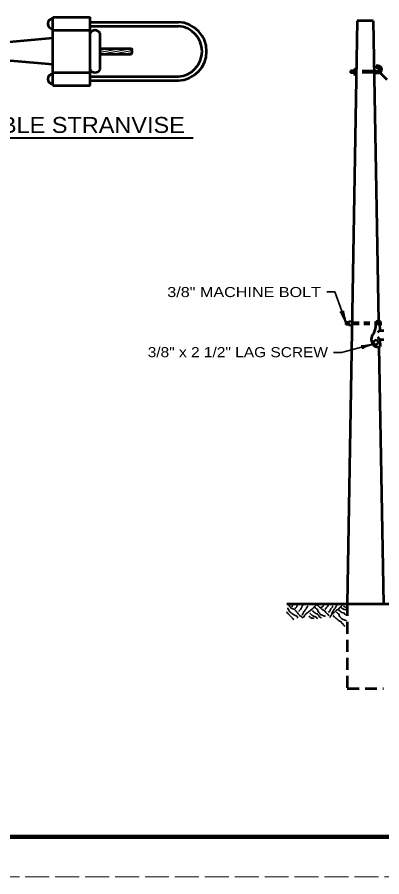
# Model space of a CAD drawing. Extents: x -1 to 679, y 0 to 440.
# Drawn here: x 228.3 to 319.7, y 0.2 to 215.6 of the extents above; entities that cross this region are included whole.
import ezdxf
from ezdxf.enums import TextEntityAlignment as Align

# ---------------------------------------------------------------- set-up
doc = ezdxf.new("R2010")
doc.units = 0
for name, pattern in [('LONG_DASHED', [7.5, 6, -1.5]), ('MEDIUM_DASHED', [4.5, 3, -1.5]), ('SHORT_DASHED', [2.7, 1.5, -1.2])]:
    doc.linetypes.add(name, pattern=pattern)
doc.layers.add('1', color=7, linetype='Continuous', lineweight=53)
doc.layers.add('61', color=7, linetype='Continuous', lineweight=35)

msp = doc.modelspace()

# ---------------------------------------------------------------- linework, layer by layer
at = {"layer": '1'}
for p, q in [((237.256, 215.614), (246.596, 215.614)), ((237.256, 212.334), (237.256, 215.614)), ((246.596, 198.474), (246.596, 215.614)), ((246.596, 214.354), (268.756, 214.354)), ((246.596, 213.354), (268.756, 213.354)), ((313.579, 214.715), (311.019, 68.575)), ((317.599, 214.715), (313.579, 214.715)), ((317.599, 214.715), (318.919, 139.375)), ((237.256, 212.334), (246.596, 212.334)), ((249.116, 202.514), (249.116, 211.594)), ((237.256, 210.334), (213.656, 208.254)), ((249.116, 207.754), (257.016, 207.754)), ((237.256, 203.774), (213.656, 205.834)), ((249.116, 206.354), (257.016, 206.354)), ((313.099, 202.895), (313.099, 200.895)), ((313.099, 202.895), (313.359, 202.895)), ((318.839, 203.415), (318.319, 203.415)), ((318.839, 202.895), (318.319, 202.895)), ((237.256, 201.754), (246.596, 201.754)), ((246.596, 200.754), (268.756, 200.754)), ((312.599, 202.155), (311.839, 202.155)), ((311.839, 202.155), (311.839, 201.635)), ((312.599, 201.635), (311.839, 201.635)), ((312.599, 202.395), (312.599, 201.395)), ((312.599, 202.395), (313.079, 202.395)), ((312.599, 201.395), (313.099, 201.395)), ((313.099, 200.895), (313.319, 200.895)), ((317.819, 202.155), (318.839, 202.155)), ((317.839, 201.635), (318.939, 201.635)), ((318.819, 202.135), (320.959, 200.015)), ((237.256, 198.474), (246.596, 198.474)), ((246.596, 199.734), (268.756, 199.734)), ((311.479, 139.115), (310.739, 139.115)), ((310.739, 139.115), (310.739, 138.615)), ((311.479, 138.615), (310.739, 138.615)), ((311.479, 138.375), (311.479, 139.375)), ((319.439, 139.375), (318.859, 139.375)), ((319.179, 138.955), (319.199, 137.135)), ((319.439, 138.375), (319.179, 138.375)), ((319.439, 139.375), (319.439, 138.375)), ((319.199, 137.135), (318.679, 136.595)), ((319.199, 137.135), (320.259, 137.135)), ((317.459, 134.275), (318.279, 134.855)), ((317.459, 134.275), (318.039, 133.435)), ((318.039, 133.435), (318.859, 134.015)), ((318.279, 134.855), (318.859, 134.015)), ((319.239, 134.875), (318.719, 135.415)), ((319.239, 134.875), (319.279, 133.115)), ((319.239, 134.875), (320.259, 134.875)), ((319.019, 133.035), (320.159, 68.575)), ((295.899, 68.575), (484.219, 68.575))]:
    msp.add_line(p, q, dxfattribs=at)
at = {"layer": '1', "lineweight": 25}
for p, q in [((249.116, 206.354), (257.016, 207.754)), ((249.116, 207.374), (251.296, 207.754)), ((249.116, 206.854), (254.156, 207.754)), ((251.976, 206.354), (256.996, 207.254)), ((254.836, 206.354), (257.076, 206.754))]:
    msp.add_line(p, q, dxfattribs=at)
at = {"layer": '1', "linetype": 'MEDIUM_DASHED', "lineweight": 40}
for p, q in [((317.839, 201.635), (313.339, 201.635)), ((317.819, 202.155), (313.359, 202.155))]:
    msp.add_line(p, q, dxfattribs=at)
at = {"layer": '1', "lineweight": 40}
for p, q in [((215.436, 185.414), (272.476, 185.414)), ((312.259, 139.375), (311.479, 139.375)), ((312.239, 138.375), (311.479, 138.375))]:
    msp.add_line(p, q, dxfattribs=at)
at = {"layer": '1', "linetype": 'SHORT_DASHED', "lineweight": 40}
for p, q in [((319.439, 138.615), (312.239, 138.615)), ((319.419, 139.115), (312.259, 139.115))]:
    msp.add_line(p, q, dxfattribs=at)
at = {"layer": '1', "linetype": 'MEDIUM_DASHED'}
for p, q in [((311.019, 68.575), (311.019, 47.415)), ((311.019, 47.415), (320.159, 47.415))]:
    msp.add_line(p, q, dxfattribs=at)
at = {"layer": '1'}
msp.add_lwpolyline([(237.256, 198.474), (237.256, 201.754), (237.256, 212.334)], dxfattribs=at)
at = {"layer": '1', "lineweight": 35}
for points in [[(310.699, 139.175), (307.939, 146.755), (305.919, 146.755)], [(317.439, 133.655), (309.659, 131.575), (307.639, 131.575)]]:
    msp.add_lwpolyline(points, dxfattribs=at)
at = {"layer": '1'}
for centre, radius, start, end in [((237.264, 213.982), 1.26, 90, 270), ((268.507, 207.052), 7.312, 272.01017, 87.98983), ((268.367, 207.052), 6.312, 273.59778, 86.40223), ((247.848, 210.916), 1.428, 28.07249, 151.92751), ((247.848, 203.187), 1.428, 208.07249, 331.92751), ((318.612, 203.153), 0.381, 138.58649, 221.41351), ((318.808, 202.518), 0.887, 278.54206, 88.56984), ((318.7, 202.523), 0.4, 289.03349, 70.96651), ((237.264, 200.122), 1.26, 90, 270), ((314.182, 138.306), 4.014, 331.99837, 353.85569), ((320.301, 138.299), 2.168, 151.6071, 191.23066), ((318.674, 138.91), 0.505, 5.14198, 123.76222), ((319.372, 134.854), 2.272, 136.38146, 225.27926), ((318.67, 134.82), 1.818, 240.4205, 289.57853)]:
    msp.add_arc(centre, radius, start, end, dxfattribs=at)
at = {"layer": '1', "lineweight": 40}
for centre, major_axis, ratio, start_param, end_param in [((310.056, 140.123), (0.764, -1.638), 0.122415, 0.8963533, 3.1415927), ((310.508, 140.319), (0.439, -1.724), 0.07063, 3.1407148, 5.41811), ((316.294, 133.568), (-1.756, -0.287), 0.07063, 6.2823074, 8.5597026), ((316.45, 133.101), (1.698, 0.618), 0.122415, 0.8963533, 3.1415927)]:
    msp.add_ellipse(centre, major_axis=major_axis, ratio=ratio, start_param=start_param, end_param=end_param, dxfattribs=at)
at = {"layer": '1'}
msp.add_spline([(257.016, 207.754), (257.096, 207.614), (257.036, 207.534), (257.056, 207.374), (256.996, 207.254), (257.076, 207.134), (257.036, 207.034), (257.076, 206.854), (257.056, 206.714), (256.996, 206.594), (257.016, 206.534), (257.016, 206.354)], degree=3, dxfattribs=at)
at = {"layer": '1', "lineweight": 35}
for points in [[(296.139, 67.635), (296.279, 67.255), (296.539, 66.835), (296.859, 66.415), (297.179, 66.215), (297.719, 65.835), (298.599, 65.255), (298.619, 64.995)], [(296.359, 68.455), (297.019, 67.555), (297.859, 67.155), (298.359, 66.635), (298.619, 66.315), (298.939, 65.935), (299.199, 65.615), (299.599, 65.415), (299.919, 65.035)], [(297.519, 68.375), (297.439, 68.255), (297.399, 68.255), (297.339, 68.175), (297.179, 67.895), (297.139, 67.835)], [(298.719, 68.335), (298.519, 68.175), (298.459, 68.015), (298.399, 67.835), (298.279, 67.695), (298.199, 67.635), (297.919, 67.415)], [(299.979, 68.255), (299.779, 68.055), (299.659, 67.735), (299.499, 67.415), (299.139, 67.015), (299.019, 66.835), (298.939, 66.735)], [(301.239, 68.055), (300.939, 67.735), (300.779, 67.375), (300.519, 67.095), (300.339, 66.795), (300.139, 66.575), (300.039, 66.335), (299.919, 66.115), (299.759, 65.795)], [(303.179, 68.455), (303.179, 68.315), (303.099, 68.135), (302.979, 67.995), (302.859, 67.875), (302.599, 67.615), (302.399, 67.415), (301.819, 66.975), (301.499, 66.715), (300.859, 66.195), (300.599, 65.935), (300.459, 65.735), (300.279, 65.475), (300.079, 65.155)], [(302.339, 66.955), (302.819, 66.475), (302.919, 66.435), (303.019, 66.335), (303.439, 66.095), (303.939, 65.635), (304.099, 65.375), (304.599, 65.095)], [(302.979, 67.675), (303.179, 67.535), (303.359, 67.375), (303.719, 66.935), (303.759, 66.635), (304.019, 66.415), (304.099, 66.255), (304.759, 65.755), (305.139, 65.635), (305.239, 65.575), (305.599, 65.415)], [(303.399, 68.415), (303.919, 67.955), (304.359, 67.575), (305.139, 66.995), (305.339, 66.935), (305.519, 66.675), (305.839, 66.295), (306.239, 65.895), (306.419, 65.635)], [(304.559, 67.695), (305.019, 68.015), (305.099, 68.155), (305.259, 68.375)], [(305.419, 67.255), (305.779, 67.515), (306.019, 67.835), (306.079, 67.915), (306.199, 68.055), (306.399, 68.275)], [(306.259, 66.515), (306.719, 66.755), (306.779, 67.055), (307.199, 67.575), (307.339, 67.735), (307.399, 67.995), (307.419, 68.115)], [(309.759, 68.475), (309.759, 68.335), (309.699, 68.155), (309.559, 68.015), (309.439, 67.895), (309.179, 67.635), (308.979, 67.435), (308.399, 66.995), (308.079, 66.735), (307.439, 66.215), (307.179, 65.955), (307.059, 65.755), (306.859, 65.495), (306.659, 65.175)], [(308.599, 68.315), (308.299, 67.995), (308.139, 67.655), (307.879, 67.355), (307.699, 67.075), (307.499, 66.835), (307.399, 66.615), (307.279, 66.395), (307.119, 66.075)], [(308.859, 67.155), (309.279, 66.775), (309.439, 66.655), (309.719, 66.455), (310.299, 66.235), (310.499, 65.995), (310.779, 65.875)], [(309.499, 67.655), (309.719, 67.535), (310.139, 67.235), (310.199, 67.215), (310.399, 67.215), (310.819, 67.135)], [(310.099, 68.095), (310.219, 67.995), (310.219, 67.975), (310.279, 67.915), (310.579, 67.755), (310.639, 67.715)], [(295.879, 66.595), (296.019, 66.375), (296.279, 66.115), (296.599, 65.735), (296.879, 65.535), (297.139, 65.215), (297.399, 64.955), (297.659, 64.635)], [(301.439, 65.475), (301.659, 65.355), (302.079, 65.055), (302.139, 65.015), (302.339, 65.015), (302.759, 64.955)], [(301.719, 66.255), (302.139, 65.855), (302.299, 65.735), (302.599, 65.535), (303.179, 65.315), (303.359, 65.095), (303.659, 64.955)], [(307.479, 65.695), (307.979, 65.235), (308.439, 64.855), (309.219, 64.275), (309.399, 64.215), (309.599, 63.955), (309.919, 63.555), (310.319, 63.175), (310.499, 62.915)], [(308.279, 66.595), (308.479, 66.455), (308.659, 66.295), (309.019, 65.835), (309.059, 65.555), (309.319, 65.335), (309.399, 65.175), (310.059, 64.675), (310.439, 64.555), (310.539, 64.495), (310.899, 64.335)]]:
    msp.add_spline(points, degree=3, dxfattribs=at)
at = {"layer": '61', "lineweight": 158}
msp.add_line((667.931, 10.202), (28.871, 10.222), dxfattribs=at)
at = {"layer": '61', "linetype": 'LONG_DASHED', "lineweight": 13}
msp.add_line((678.871, 0.222), (-1.189, 0.202), dxfattribs=at)

# ---------------------------------------------------------------- texts
at = {"layer": '1', "width": 1.1}
msp.add_text('CABLE STRANVISE', height=4, dxfattribs=at).set_placement((216.081, 186.607))
at = {"layer": '1'}
for s, width, p in [('3/8" MACHINE BOLT', 1.2, (304.471, 145.475)), ('3/8" x 2 1/2" LAG SCREW', 1.15, (306.232, 130.415))]:
    msp.add_text(s, height=2.52, dxfattribs=dict(at, width=width)).set_placement(p, align=Align.RIGHT)

doc.saveas('drawing.dxf')
